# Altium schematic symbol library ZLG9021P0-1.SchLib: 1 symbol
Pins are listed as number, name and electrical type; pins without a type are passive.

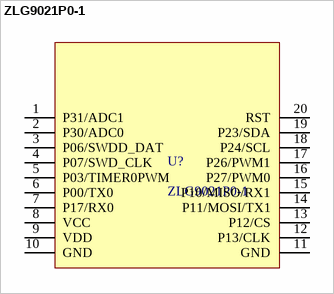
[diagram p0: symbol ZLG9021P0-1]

## ZLG9021P0-1
designator U?
pins: 1 P31/ADC1, 2 P30/ADC0, 3 P06/SWDD_DAT, 4 P07/SWD_CLK, 5 P03/TIMER0PWM, 6 P00/TX0, 7 P17/RX0, 8 VCC, 9 VDD, 10 GND, 11 GND, 12 P13/CLK, 13 P12/CS, 14 P11/MOSI/TX1, 15 P10/MISO/RX1, 16 P27/PWM0, 17 P26/PWM1, 18 P24/SCL, 19 P23/SDA, 20 RST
